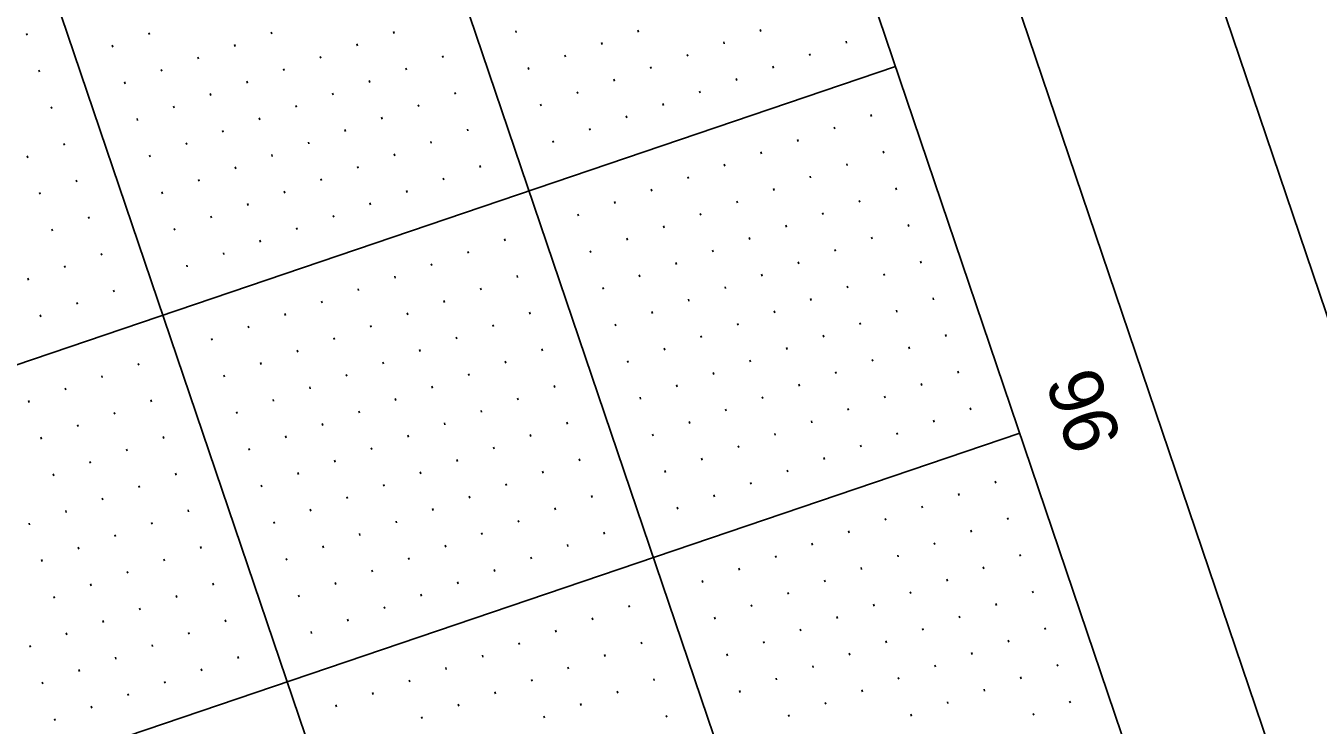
# Model space of a CAD drawing. Extents: x 2150318 to 2152065, y 143281 to 145371.
# Drawn here: x 2151482.1 to 2151649.1, y 144558.8 to 144649.2 of the extents above; entities that cross this region are included whole.
import ezdxf

# ---------------------------------------------------------------- set-up
doc = ezdxf.new("R2010")
doc.units = 0
for name, color, linetype in [('SHT_Plan_Profile_Sheet_Sta_Txt', 7, 'Continuous'), ('SHT_Plot_Shape_Half', 7, 'Continuous'), ('SHT_Profile_Grid_Major', 7, 'Continuous'), ('SHT_Profile_Grid_Minor', 7, 'Continuous'), ('SHT_Sheet_Border', 7, 'Continuous')]:
    doc.layers.add(name, color=color, linetype=linetype)

msp = doc.modelspace()

# ---------------------------------------------------------------- linework, layer by layer
at = {"layer": 'SHT_Plot_Shape_Half'}
msp.add_lwpolyline([(2150909.49, 143371.4), (2150363.35, 144981.29), (2151405.04, 145334.68), (2151951.18, 143724.79)], close=True, dxfattribs=at)
at = {"layer": 'SHT_Profile_Grid_Major'}
for p, q in [((2151832.26, 143787.41), (2151326.27, 145278.92)), ((2151784.91, 143771.34), (2151278.93, 145262.85)), ((2151594.49, 144643.92), (2151163.61, 144497.75)), ((2151610.56, 144596.57), (2151179.68, 144450.4))]:
    msp.add_line(p, q, dxfattribs=at)
at = {"layer": 'SHT_Profile_Grid_Minor'}
for p, q in [((2151482.25, 144647.95), (2151482.17, 144648.19)), ((2151498.06, 144648.04), (2151497.98, 144648.27)), ((2151513.87, 144648.12), (2151513.79, 144648.36)), ((2151529.68, 144648.2), (2151529.6, 144648.44)), ((2151545.49, 144648.29), (2151545.41, 144648.53)), ((2151561.3, 144648.37), (2151561.22, 144648.61)), ((2151577.12, 144648.46), (2151577.03, 144648.69)), ((2151493.32, 144646.43), (2151493.24, 144646.67)), ((2151509.14, 144646.51), (2151509.06, 144646.75)), ((2151524.95, 144646.6), (2151524.87, 144646.83)), ((2151556.57, 144646.77), (2151556.49, 144647)), ((2151572.38, 144646.85), (2151572.3, 144647.09)), ((2151588.19, 144646.93), (2151588.11, 144647.17)), ((2151504.4, 144644.91), (2151504.32, 144645.14)), ((2151520.21, 144644.99), (2151520.13, 144645.23)), ((2151536.02, 144645.08), (2151535.94, 144645.31)), ((2151551.83, 144645.16), (2151551.75, 144645.4)), ((2151567.65, 144645.24), (2151567.56, 144645.48)), ((2151583.46, 144645.33), (2151583.38, 144645.56)), ((2151483.85, 144643.22), (2151483.77, 144643.45)), ((2151499.67, 144643.3), (2151499.59, 144643.54)), ((2151515.48, 144643.39), (2151515.4, 144643.62)), ((2151531.29, 144643.47), (2151531.21, 144643.71)), ((2151547.1, 144643.55), (2151547.02, 144643.79)), ((2151562.91, 144643.64), (2151562.83, 144643.87)), ((2151578.72, 144643.72), (2151578.64, 144643.96)), ((2151494.93, 144641.7), (2151494.85, 144641.93)), ((2151510.74, 144641.78), (2151510.66, 144642.02)), ((2151526.55, 144641.86), (2151526.47, 144642.1)), ((2151558.18, 144642.03), (2151558.1, 144642.27)), ((2151573.99, 144642.12), (2151573.91, 144642.35)), ((2151506.01, 144640.17), (2151505.93, 144640.41)), ((2151521.82, 144640.26), (2151521.74, 144640.49)), ((2151537.63, 144640.34), (2151537.55, 144640.58)), ((2151553.44, 144640.42), (2151553.36, 144640.66)), ((2151569.25, 144640.51), (2151569.17, 144640.75)), ((2151485.46, 144638.48), (2151485.38, 144638.72)), ((2151501.27, 144638.57), (2151501.19, 144638.8)), ((2151517.08, 144638.65), (2151517, 144638.89)), ((2151532.89, 144638.73), (2151532.81, 144638.97)), ((2151548.71, 144638.82), (2151548.63, 144639.06)), ((2151559.78, 144637.3), (2151559.7, 144637.53)), ((2151564.52, 144638.9), (2151564.44, 144639.14)), ((2151591.4, 144637.46), (2151591.32, 144637.7)), ((2151496.54, 144636.96), (2151496.46, 144637.2)), ((2151512.35, 144637.04), (2151512.27, 144637.28)), ((2151528.16, 144637.13), (2151528.08, 144637.37)), ((2151539.24, 144635.61), (2151539.16, 144635.84)), ((2151555.05, 144635.69), (2151554.97, 144635.93)), ((2151586.67, 144635.86), (2151586.59, 144636.09)), ((2151507.61, 144635.44), (2151507.53, 144635.67)), ((2151518.69, 144633.92), (2151518.61, 144634.15)), ((2151523.42, 144635.52), (2151523.34, 144635.76)), ((2151534.5, 144634), (2151534.42, 144634.24)), ((2151550.31, 144634.08), (2151550.23, 144634.32)), ((2151581.93, 144634.25), (2151581.85, 144634.49)), ((2151487.07, 144633.75), (2151486.99, 144633.98)), ((2151502.88, 144633.83), (2151502.8, 144634.07)), ((2151513.95, 144632.31), (2151513.87, 144632.55)), ((2151529.77, 144632.39), (2151529.69, 144632.63)), ((2151577.2, 144632.65), (2151577.12, 144632.88)), ((2151593.01, 144632.73), (2151592.93, 144632.97)), ((2151482.33, 144632.14), (2151482.25, 144632.38)), ((2151498.14, 144632.23), (2151498.06, 144632.46)), ((2151509.22, 144630.7), (2151509.14, 144630.94)), ((2151525.03, 144630.79), (2151524.95, 144631.02)), ((2151540.84, 144630.87), (2151540.76, 144631.11)), ((2151572.46, 144631.04), (2151572.38, 144631.28)), ((2151588.28, 144631.12), (2151588.2, 144631.36)), ((2151488.67, 144629.01), (2151488.59, 144629.25)), ((2151504.48, 144629.1), (2151504.4, 144629.33)), ((2151520.3, 144629.18), (2151520.22, 144629.42)), ((2151536.11, 144629.26), (2151536.03, 144629.5)), ((2151567.73, 144629.43), (2151567.65, 144629.67)), ((2151583.54, 144629.52), (2151583.46, 144629.75)), ((2151483.94, 144627.41), (2151483.86, 144627.64)), ((2151499.75, 144627.49), (2151499.67, 144627.73)), ((2151515.56, 144627.57), (2151515.48, 144627.81)), ((2151531.37, 144627.66), (2151531.29, 144627.9)), ((2151562.99, 144627.83), (2151562.91, 144628.06)), ((2151578.81, 144627.91), (2151578.73, 144628.15)), ((2151594.62, 144627.99), (2151594.54, 144628.23)), ((2151510.83, 144625.97), (2151510.75, 144626.2)), ((2151526.64, 144626.05), (2151526.56, 144626.29)), ((2151558.26, 144626.22), (2151558.18, 144626.46)), ((2151574.07, 144626.3), (2151573.99, 144626.54)), ((2151589.88, 144626.39), (2151589.8, 144626.62)), ((2151490.28, 144624.28), (2151490.2, 144624.51)), ((2151506.09, 144624.36), (2151506.01, 144624.6)), ((2151521.9, 144624.45), (2151521.82, 144624.68)), ((2151553.52, 144624.61), (2151553.44, 144624.85)), ((2151569.34, 144624.7), (2151569.26, 144624.93)), ((2151585.15, 144624.78), (2151585.07, 144625.02)), ((2151485.54, 144622.67), (2151485.46, 144622.91)), ((2151501.36, 144622.76), (2151501.28, 144622.99)), ((2151517.17, 144622.84), (2151517.09, 144623.08)), ((2151564.6, 144623.09), (2151564.52, 144623.33)), ((2151580.41, 144623.18), (2151580.33, 144623.41)), ((2151596.22, 144623.26), (2151596.14, 144623.5)), ((2151512.43, 144621.23), (2151512.35, 144621.47)), ((2151544.05, 144621.4), (2151543.97, 144621.64)), ((2151559.87, 144621.49), (2151559.79, 144621.72)), ((2151575.68, 144621.57), (2151575.6, 144621.81)), ((2151591.49, 144621.65), (2151591.41, 144621.89)), ((2151491.89, 144619.54), (2151491.81, 144619.78)), ((2151507.7, 144619.63), (2151507.62, 144619.86)), ((2151539.32, 144619.79), (2151539.24, 144620.03)), ((2151555.13, 144619.88), (2151555.05, 144620.12)), ((2151570.94, 144619.96), (2151570.86, 144620.2)), ((2151586.75, 144620.05), (2151586.67, 144620.28)), ((2151487.15, 144617.94), (2151487.07, 144618.17)), ((2151502.96, 144618.02), (2151502.88, 144618.26)), ((2151534.58, 144618.19), (2151534.5, 144618.43)), ((2151566.21, 144618.36), (2151566.13, 144618.59)), ((2151582.02, 144618.44), (2151581.94, 144618.68)), ((2151597.83, 144618.52), (2151597.75, 144618.76)), ((2151482.42, 144616.33), (2151482.34, 144616.57)), ((2151529.85, 144616.58), (2151529.77, 144616.82)), ((2151545.66, 144616.67), (2151545.58, 144616.9)), ((2151561.47, 144616.75), (2151561.39, 144616.99)), ((2151577.28, 144616.83), (2151577.2, 144617.07)), ((2151593.09, 144616.92), (2151593.01, 144617.15)), ((2151493.49, 144614.81), (2151493.41, 144615.04)), ((2151525.11, 144614.98), (2151525.03, 144615.21)), ((2151540.93, 144615.06), (2151540.85, 144615.3)), ((2151556.74, 144615.14), (2151556.66, 144615.38)), ((2151572.55, 144615.23), (2151572.47, 144615.46)), ((2151588.36, 144615.31), (2151588.28, 144615.55)), ((2151488.76, 144613.2), (2151488.68, 144613.44)), ((2151520.38, 144613.37), (2151520.3, 144613.61)), ((2151536.19, 144613.45), (2151536.11, 144613.69)), ((2151567.81, 144613.62), (2151567.73, 144613.86)), ((2151583.62, 144613.71), (2151583.54, 144613.94)), ((2151594.7, 144612.18), (2151594.62, 144612.42)), ((2151599.44, 144613.79), (2151599.36, 144614.03)), ((2151484.02, 144611.6), (2151483.94, 144611.83)), ((2151515.64, 144611.76), (2151515.56, 144612)), ((2151531.46, 144611.85), (2151531.38, 144612.08)), ((2151547.27, 144611.93), (2151547.19, 144612.17)), ((2151563.08, 144612.02), (2151563, 144612.25)), ((2151578.89, 144612.1), (2151578.81, 144612.34)), ((2151589.97, 144610.58), (2151589.89, 144610.81)), ((2151510.91, 144610.16), (2151510.83, 144610.39)), ((2151526.72, 144610.24), (2151526.64, 144610.48)), ((2151542.53, 144610.32), (2151542.45, 144610.56)), ((2151558.34, 144610.41), (2151558.26, 144610.65)), ((2151569.42, 144608.89), (2151569.34, 144609.12)), ((2151574.15, 144610.49), (2151574.07, 144610.73)), ((2151585.23, 144608.97), (2151585.15, 144609.21)), ((2151601.04, 144609.05), (2151600.96, 144609.29)), ((2151506.17, 144608.55), (2151506.09, 144608.79)), ((2151521.99, 144608.63), (2151521.91, 144608.87)), ((2151537.8, 144608.72), (2151537.72, 144608.96)), ((2151548.87, 144607.2), (2151548.79, 144607.43)), ((2151564.68, 144607.28), (2151564.6, 144607.52)), ((2151580.5, 144607.36), (2151580.42, 144607.6)), ((2151596.31, 144607.45), (2151596.23, 144607.69)), ((2151517.25, 144607.03), (2151517.17, 144607.27)), ((2151528.33, 144605.51), (2151528.25, 144605.74)), ((2151533.06, 144607.11), (2151532.98, 144607.35)), ((2151544.14, 144605.59), (2151544.06, 144605.83)), ((2151559.95, 144605.67), (2151559.87, 144605.91)), ((2151575.76, 144605.76), (2151575.68, 144605.99)), ((2151591.57, 144605.84), (2151591.49, 144606.08)), ((2151496.71, 144605.34), (2151496.62, 144605.57)), ((2151512.52, 144605.42), (2151512.44, 144605.66)), ((2151523.59, 144603.9), (2151523.51, 144604.14)), ((2151539.4, 144603.98), (2151539.32, 144604.22)), ((2151571.03, 144604.15), (2151570.95, 144604.39)), ((2151586.84, 144604.24), (2151586.76, 144604.47)), ((2151602.65, 144604.32), (2151602.57, 144604.56)), ((2151491.97, 144603.73), (2151491.89, 144603.97)), ((2151507.78, 144603.82), (2151507.7, 144604.05)), ((2151518.86, 144602.29), (2151518.78, 144602.53)), ((2151534.67, 144602.38), (2151534.59, 144602.61)), ((2151550.48, 144602.46), (2151550.4, 144602.7)), ((2151566.29, 144602.55), (2151566.21, 144602.78)), ((2151582.1, 144602.63), (2151582.02, 144602.87)), ((2151597.91, 144602.71), (2151597.83, 144602.95)), ((2151482.5, 144600.52), (2151482.42, 144600.76)), ((2151487.24, 144602.13), (2151487.15, 144602.36)), ((2151498.31, 144600.6), (2151498.23, 144600.84)), ((2151514.12, 144600.69), (2151514.04, 144600.92)), ((2151529.93, 144600.77), (2151529.85, 144601.01)), ((2151545.74, 144600.86), (2151545.66, 144601.09)), ((2151561.56, 144600.94), (2151561.48, 144601.18)), ((2151577.37, 144601.02), (2151577.29, 144601.26)), ((2151593.18, 144601.11), (2151593.1, 144601.34)), ((2151493.58, 144599), (2151493.5, 144599.23)), ((2151509.39, 144599.08), (2151509.31, 144599.32)), ((2151525.2, 144599.16), (2151525.12, 144599.4)), ((2151541.01, 144599.25), (2151540.93, 144599.49)), ((2151572.63, 144599.42), (2151572.55, 144599.65)), ((2151588.44, 144599.5), (2151588.36, 144599.74)), ((2151604.25, 144599.58), (2151604.17, 144599.82)), ((2151488.84, 144597.39), (2151488.76, 144597.63)), ((2151520.46, 144597.56), (2151520.38, 144597.8)), ((2151536.27, 144597.64), (2151536.19, 144597.88)), ((2151552.09, 144597.73), (2151552.01, 144597.96)), ((2151567.9, 144597.81), (2151567.82, 144598.05)), ((2151583.71, 144597.89), (2151583.63, 144598.13)), ((2151599.52, 144597.98), (2151599.44, 144598.22)), ((2151484.11, 144595.78), (2151484.03, 144596.02)), ((2151499.92, 144595.87), (2151499.84, 144596.1)), ((2151515.73, 144595.95), (2151515.65, 144596.19)), ((2151531.54, 144596.04), (2151531.46, 144596.27)), ((2151547.35, 144596.12), (2151547.27, 144596.36)), ((2151563.16, 144596.2), (2151563.08, 144596.44)), ((2151578.97, 144596.29), (2151578.89, 144596.52)), ((2151594.78, 144596.37), (2151594.7, 144596.61)), ((2151495.18, 144594.26), (2151495.1, 144594.5)), ((2151510.99, 144594.35), (2151510.91, 144594.58)), ((2151526.81, 144594.43), (2151526.72, 144594.67)), ((2151542.62, 144594.51), (2151542.54, 144594.75)), ((2151574.24, 144594.68), (2151574.16, 144594.92)), ((2151590.05, 144594.77), (2151589.97, 144595)), ((2151490.45, 144592.66), (2151490.37, 144592.89)), ((2151522.07, 144592.82), (2151521.99, 144593.06)), ((2151537.88, 144592.91), (2151537.8, 144593.14)), ((2151553.69, 144592.99), (2151553.61, 144593.23)), ((2151569.5, 144593.08), (2151569.42, 144593.31)), ((2151585.31, 144593.16), (2151585.23, 144593.4)), ((2151485.71, 144591.05), (2151485.63, 144591.29)), ((2151501.52, 144591.13), (2151501.44, 144591.37)), ((2151517.34, 144591.22), (2151517.25, 144591.45)), ((2151533.15, 144591.3), (2151533.07, 144591.54)), ((2151548.96, 144591.39), (2151548.88, 144591.62)), ((2151564.77, 144591.47), (2151564.69, 144591.71)), ((2151580.58, 144591.55), (2151580.5, 144591.79)), ((2151496.79, 144589.53), (2151496.71, 144589.76)), ((2151512.6, 144589.61), (2151512.52, 144589.85)), ((2151528.41, 144589.69), (2151528.33, 144589.93)), ((2151544.22, 144589.78), (2151544.14, 144590.02)), ((2151575.84, 144589.95), (2151575.76, 144590.18)), ((2151607.47, 144590.11), (2151607.39, 144590.35)), ((2151492.05, 144587.92), (2151491.97, 144588.16)), ((2151523.68, 144588.09), (2151523.6, 144588.33)), ((2151539.49, 144588.17), (2151539.41, 144588.41)), ((2151555.3, 144588.26), (2151555.22, 144588.49)), ((2151571.11, 144588.34), (2151571.03, 144588.58)), ((2151602.73, 144588.51), (2151602.65, 144588.75)), ((2151487.32, 144586.31), (2151487.24, 144586.55)), ((2151503.13, 144586.4), (2151503.05, 144586.63)), ((2151518.94, 144586.48), (2151518.86, 144586.72)), ((2151534.75, 144586.57), (2151534.67, 144586.8)), ((2151550.56, 144586.65), (2151550.48, 144586.89)), ((2151566.37, 144586.73), (2151566.29, 144586.97)), ((2151598, 144586.9), (2151597.92, 144587.14)), ((2151482.58, 144584.71), (2151482.5, 144584.94)), ((2151498.4, 144584.79), (2151498.32, 144585.03)), ((2151514.21, 144584.88), (2151514.13, 144585.11)), ((2151530.02, 144584.96), (2151529.94, 144585.2)), ((2151545.83, 144585.04), (2151545.75, 144585.28)), ((2151593.26, 144585.3), (2151593.18, 144585.53)), ((2151609.07, 144585.38), (2151608.99, 144585.62)), ((2151493.66, 144583.19), (2151493.58, 144583.42)), ((2151525.28, 144583.35), (2151525.2, 144583.59)), ((2151541.09, 144583.44), (2151541.01, 144583.67)), ((2151556.91, 144583.52), (2151556.82, 144583.76)), ((2151588.53, 144583.69), (2151588.45, 144583.93)), ((2151599.6, 144582.17), (2151599.52, 144582.4)), ((2151604.34, 144583.77), (2151604.26, 144584.01)), ((2151488.93, 144581.58), (2151488.85, 144581.82)), ((2151504.74, 144581.66), (2151504.66, 144581.9)), ((2151520.55, 144581.75), (2151520.47, 144581.98)), ((2151536.36, 144581.83), (2151536.28, 144582.07)), ((2151552.17, 144581.92), (2151552.09, 144582.15)), ((2151579.06, 144580.48), (2151578.98, 144580.71)), ((2151583.79, 144582.08), (2151583.71, 144582.32)), ((2151594.87, 144580.56), (2151594.79, 144580.8)), ((2151610.68, 144580.64), (2151610.6, 144580.88)), ((2151484.19, 144579.97), (2151484.11, 144580.21)), ((2151500, 144580.06), (2151499.92, 144580.29)), ((2151515.81, 144580.14), (2151515.73, 144580.38)), ((2151531.62, 144580.22), (2151531.54, 144580.46)), ((2151547.44, 144580.31), (2151547.35, 144580.55)), ((2151574.32, 144578.87), (2151574.24, 144579.11)), ((2151590.13, 144578.95), (2151590.05, 144579.19)), ((2151605.94, 144579.04), (2151605.86, 144579.28)), ((2151495.27, 144578.45), (2151495.19, 144578.69)), ((2151526.89, 144578.62), (2151526.81, 144578.86)), ((2151542.7, 144578.7), (2151542.62, 144578.94)), ((2151569.59, 144577.26), (2151569.51, 144577.5)), ((2151585.4, 144577.35), (2151585.32, 144577.58)), ((2151601.21, 144577.43), (2151601.13, 144577.67)), ((2151490.53, 144576.84), (2151490.45, 144577.08)), ((2151506.34, 144576.93), (2151506.26, 144577.17)), ((2151522.15, 144577.01), (2151522.07, 144577.25)), ((2151533.23, 144575.49), (2151533.15, 144575.73)), ((2151537.97, 144577.1), (2151537.88, 144577.33)), ((2151580.66, 144575.74), (2151580.58, 144575.98)), ((2151596.47, 144575.83), (2151596.39, 144576.06)), ((2151612.29, 144575.91), (2151612.21, 144576.15)), ((2151485.8, 144575.24), (2151485.72, 144575.47)), ((2151501.61, 144575.32), (2151501.53, 144575.56)), ((2151517.42, 144575.41), (2151517.34, 144575.64)), ((2151528.5, 144573.88), (2151528.42, 144574.12)), ((2151560.12, 144574.05), (2151560.04, 144574.29)), ((2151575.93, 144574.14), (2151575.85, 144574.37)), ((2151591.74, 144574.22), (2151591.66, 144574.46)), ((2151607.55, 144574.3), (2151607.47, 144574.54)), ((2151492.14, 144572.11), (2151492.06, 144572.35)), ((2151496.87, 144573.72), (2151496.79, 144573.95)), ((2151507.95, 144572.19), (2151507.87, 144572.43)), ((2151523.76, 144572.28), (2151523.68, 144572.51)), ((2151555.38, 144572.45), (2151555.3, 144572.68)), ((2151571.19, 144572.53), (2151571.11, 144572.77)), ((2151587.01, 144572.61), (2151586.92, 144572.85)), ((2151602.82, 144572.7), (2151602.74, 144572.93)), ((2151487.4, 144570.5), (2151487.32, 144570.74)), ((2151503.21, 144570.59), (2151503.13, 144570.82)), ((2151519.03, 144570.67), (2151518.95, 144570.91)), ((2151550.65, 144570.84), (2151550.57, 144571.08)), ((2151582.27, 144571.01), (2151582.19, 144571.24)), ((2151598.08, 144571.09), (2151598, 144571.33)), ((2151613.89, 144571.17), (2151613.81, 144571.41)), ((2151482.67, 144568.9), (2151482.59, 144569.13)), ((2151498.48, 144568.98), (2151498.4, 144569.22)), ((2151545.91, 144569.23), (2151545.83, 144569.47)), ((2151561.72, 144569.32), (2151561.64, 144569.55)), ((2151577.54, 144569.4), (2151577.45, 144569.64)), ((2151593.35, 144569.48), (2151593.27, 144569.72)), ((2151609.16, 144569.57), (2151609.08, 144569.81)), ((2151493.74, 144567.37), (2151493.66, 144567.61)), ((2151509.56, 144567.46), (2151509.48, 144567.7)), ((2151541.18, 144567.63), (2151541.1, 144567.86)), ((2151556.99, 144567.71), (2151556.91, 144567.95)), ((2151572.8, 144567.79), (2151572.72, 144568.03)), ((2151588.61, 144567.88), (2151588.53, 144568.12)), ((2151604.42, 144567.96), (2151604.34, 144568.2)), ((2151489.01, 144565.77), (2151488.93, 144566)), ((2151504.82, 144565.85), (2151504.74, 144566.09)), ((2151536.44, 144566.02), (2151536.36, 144566.26)), ((2151552.25, 144566.1), (2151552.17, 144566.34)), ((2151583.88, 144566.27), (2151583.8, 144566.51)), ((2151599.69, 144566.36), (2151599.61, 144566.59)), ((2151615.5, 144566.44), (2151615.42, 144566.68)), ((2151484.27, 144564.16), (2151484.19, 144564.4)), ((2151500.09, 144564.25), (2151500.01, 144564.48)), ((2151531.71, 144564.41), (2151531.63, 144564.65)), ((2151547.52, 144564.5), (2151547.44, 144564.73)), ((2151563.33, 144564.58), (2151563.25, 144564.82)), ((2151579.14, 144564.67), (2151579.06, 144564.9)), ((2151594.95, 144564.75), (2151594.87, 144564.99)), ((2151610.76, 144564.83), (2151610.68, 144565.07)), ((2151495.35, 144562.64), (2151495.27, 144562.88)), ((2151526.97, 144562.81), (2151526.89, 144563.04)), ((2151542.78, 144562.89), (2151542.7, 144563.13)), ((2151558.6, 144562.98), (2151558.52, 144563.21)), ((2151574.41, 144563.06), (2151574.33, 144563.3)), ((2151590.22, 144563.14), (2151590.14, 144563.38)), ((2151606.03, 144563.23), (2151605.95, 144563.46)), ((2151490.62, 144561.03), (2151490.54, 144561.27)), ((2151522.24, 144561.2), (2151522.16, 144561.44)), ((2151538.05, 144561.29), (2151537.97, 144561.52)), ((2151553.86, 144561.37), (2151553.78, 144561.61)), ((2151585.48, 144561.54), (2151585.4, 144561.77)), ((2151601.29, 144561.62), (2151601.21, 144561.86)), ((2151617.11, 144561.71), (2151617.02, 144561.94)), ((2151485.88, 144559.43), (2151485.8, 144559.66)), ((2151533.31, 144559.68), (2151533.23, 144559.92)), ((2151549.13, 144559.76), (2151549.05, 144560)), ((2151564.94, 144559.85), (2151564.86, 144560.08)), ((2151580.75, 144559.93), (2151580.67, 144560.17)), ((2151596.56, 144560.01), (2151596.48, 144560.25)), ((2151612.37, 144560.1), (2151612.29, 144560.34))]:
    msp.add_line(p, q, dxfattribs=at)
at = {"layer": 'SHT_Sheet_Border'}
msp.add_line((2151879.61, 143803.47), (2151457.96, 145046.39), dxfattribs=at)
msp.add_lwpolyline([(2150901.85, 143471.77), (2150395.86, 144963.28), (2151390.2, 145300.6), (2151896.19, 143809.09)], close=True, dxfattribs=at)

# ---------------------------------------------------------------- texts
at = {"layer": 'SHT_Plan_Profile_Sheet_Sta_Txt'}
msp.add_text('96', height=7, rotation=108.7393, dxfattribs=at).set_placement((2151623.81, 144595.64))

doc.saveas('drawing.dxf')
